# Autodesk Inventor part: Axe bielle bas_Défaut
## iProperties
Shininess: 64.0
Length Units: 11269
Angle Units: 11279
Time Units: 11290
Mass Units: 11283
Length Display Precision: 3
Angle Display Precision: 2
Compacted: True
Part Number: Axe bielle bas_Défaut
Document SubType Name: Modeling
Created: 2006-01
Material: Par défaut
Designer: riri
Density: 0.0
Volumn: 0.0
Area: 0.0
PropertySet Name: Model Information
Control State: 0
Master: False
Checked Out: False
Author: riri
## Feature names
1. Base1
